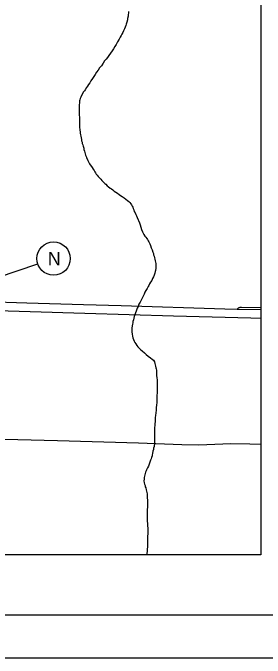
# Model space of a CAD drawing. Extents: x 1651.5 to 1685.5, y 1084.6 to 1106.6.
# Drawn here: x 1665.81 to 1668.74, y 1084.6 to 1092.09 of the extents above; entities that cross this region are included whole.
import ezdxf

# ---------------------------------------------------------------- set-up
doc = ezdxf.new("R2010")
doc.units = 0
for name, color, linetype in [('GM_X_County_Road', 7, 'Continuous'), ('GM_X_Interchange_Ramps', 7, 'Continuous'), ('GM_X_Minor_River', 7, 'Continuous'), ('GM_X_State_Route', 7, 'Continuous'), ('SC_Scratch1', 7, 'Continuous'), ('SH_Border', 7, 'Continuous'), ('SH_Data', 7, 'Continuous'), ('SH_Text', 7, 'Continuous')]:
    doc.layers.add(name, color=color, linetype=linetype)

msp = doc.modelspace()

# ---------------------------------------------------------------- linework, layer by layer
at = {"layer": 'GM_X_County_Road'}
msp.add_lwpolyline([(1664.5355, 1087.1696), (1664.9949, 1087.1576), (1665.8697, 1087.1385), (1666.329, 1087.1234), (1667.2696, 1087.0978), (1667.7725, 1087.0776), (1667.9694, 1087.0752), (1668.3411, 1087.089), (1668.5599, 1087.0865), (1668.6882, 1087.0829)], dxfattribs=at)
at = {"layer": 'GM_X_Interchange_Ramps'}
msp.add_lwpolyline([(1668.6882, 1088.6662), (1668.4646, 1088.6689), (1668.4591, 1088.6687), (1668.4539, 1088.6681), (1668.4487, 1088.6676), (1668.4426, 1088.6666), (1668.4361, 1088.6647), (1668.4322, 1088.6634), (1668.4284, 1088.6617), (1668.424, 1088.6596), (1668.4194, 1088.6571), (1668.4149, 1088.6535), (1668.4116, 1088.6492)], dxfattribs=at)
at = {"layer": 'GM_X_Minor_River'}
for points in [[(1667.1537, 1092.1007), (1667.1537, 1092.0846), (1667.151, 1092.0685), (1667.1482, 1092.0472), (1667.1428, 1092.0231), (1667.1401, 1092.007), (1667.132, 1091.9803), (1667.1266, 1091.9563), (1667.1213, 1091.9402), (1667.1132, 1091.9215), (1667.1051, 1091.9001), (1667.097, 1091.8788), (1667.0863, 1091.8574), (1667.0755, 1091.8387), (1667.0675, 1091.8227), (1667.0567, 1091.804), (1667.046, 1091.7826), (1667.0272, 1091.7506), (1667.0084, 1091.7212), (1666.9949, 1091.6945), (1666.9788, 1091.6705), (1666.9627, 1091.6464), (1666.9439, 1091.6171), (1666.9251, 1091.5904), (1666.909, 1091.569)], [(1666.909, 1091.569), (1666.8929, 1091.5503), (1666.8768, 1091.529), (1666.8607, 1091.5049), (1666.8419, 1091.4729), (1666.8178, 1091.4489), (1666.8016, 1091.4222), (1666.7829, 1091.3982), (1666.7667, 1091.3715), (1666.7506, 1091.3501), (1666.7372, 1091.3261), (1666.7184, 1091.2994), (1666.705, 1091.2754), (1666.6889, 1091.2567), (1666.6781, 1091.238), (1666.6674, 1091.2193), (1666.6513, 1091.1953), (1666.6432, 1091.1819), (1666.6325, 1091.1686), (1666.6083, 1091.1285), (1666.6002, 1091.1071), (1666.5922, 1091.0911), (1666.5895, 1091.0777), (1666.5868, 1091.0644), (1666.584, 1091.0403), (1666.5813, 1091.0243), (1666.5813, 1091.0109), (1666.5812, 1090.9948), (1666.5812, 1090.9788), (1666.5812, 1090.9627), (1666.5811, 1090.9413), (1666.5811, 1090.9226), (1666.581, 1090.9012), (1666.5836, 1090.8771), (1666.5836, 1090.8584), (1666.5835, 1090.8343), (1666.5835, 1090.8075), (1666.5834, 1090.7835), (1666.5834, 1090.7647), (1666.586, 1090.7513), (1666.5887, 1090.7379), (1666.5887, 1090.7246), (1666.5913, 1090.7059), (1666.5939, 1090.6925), (1666.5965, 1090.6711), (1666.6019, 1090.655), (1666.6045, 1090.6362), (1666.6071, 1090.6175), (1666.6098, 1090.6015), (1666.6151, 1090.588), (1666.6177, 1090.572), (1666.623, 1090.5559), (1666.6257, 1090.5399), (1666.6337, 1090.5158), (1666.6363, 1090.5024), (1666.6416, 1090.4809), (1666.6469, 1090.4649), (1666.6522, 1090.4515), (1666.6549, 1090.4354), (1666.6629, 1090.422), (1666.6655, 1090.4059), (1666.6735, 1090.3925), (1666.6815, 1090.3738), (1666.6921, 1090.3524), (1666.7028, 1090.3336), (1666.7321, 1090.2907), (1666.7428, 1090.2746), (1666.7535, 1090.2585), (1666.7615, 1090.2424), (1666.7721, 1090.229), (1666.7801, 1090.2156), (1666.7881, 1090.2022), (1666.8015, 1090.1888), (1666.8175, 1090.1727), (1666.8308, 1090.1566), (1666.8442, 1090.1432), (1666.8575, 1090.1298), (1666.8789, 1090.1083), (1666.8922, 1090.0976), (1666.9056, 1090.0815), (1666.9189, 1090.0734), (1666.9403, 1090.0546), (1666.9563, 1090.0438), (1666.9697, 1090.0331), (1666.9884, 1090.0197), (1667.0044, 1090.0062), (1667.0258, 1089.9928), (1667.0445, 1089.9793), (1667.0605, 1089.9686), (1667.0792, 1089.9578), (1667.1033, 1089.9417), (1667.122, 1089.9256), (1667.1433, 1089.9095), (1667.1567, 1089.8987), (1667.17, 1089.8853), (1667.1807, 1089.8719), (1667.1887, 1089.8585), (1667.194, 1089.8451), (1667.202, 1089.8317), (1667.2073, 1089.8183), (1667.2153, 1089.7995)], [(1667.2153, 1089.7995), (1667.2206, 1089.7808), (1667.2313, 1089.7674), (1667.2393, 1089.7486), (1667.2473, 1089.7299), (1667.2553, 1089.7111), (1667.2792, 1089.6495), (1667.2872, 1089.6281), (1667.2951, 1089.6013), (1667.3031, 1089.5718), (1667.3137, 1089.5451), (1667.3297, 1089.5156), (1667.3431, 1089.4968), (1667.3537, 1089.4834), (1667.3644, 1089.47), (1667.3724, 1089.4566), (1667.3804, 1089.4432), (1667.3884, 1089.4298), (1667.3991, 1089.4083), (1667.407, 1089.3869), (1667.4177, 1089.3601), (1667.4283, 1089.336), (1667.4336, 1089.3119), (1667.4416, 1089.2931), (1667.4443, 1089.2798), (1667.4496, 1089.2637), (1667.4549, 1089.2449), (1667.4575, 1089.2289), (1667.4628, 1089.2101), (1667.4655, 1089.1941), (1667.4681, 1089.178), (1667.4681, 1089.162), (1667.468, 1089.1405), (1667.468, 1089.1245), (1667.4652, 1089.0978), (1667.4625, 1089.0844), (1667.4571, 1089.0657), (1667.4517, 1089.0443), (1667.4437, 1089.0256), (1667.4329, 1089.0042), (1667.4222, 1088.9829), (1667.4087, 1088.9615), (1667.398, 1088.9428), (1667.3899, 1088.9241), (1667.3792, 1088.9108), (1667.3711, 1088.8867), (1667.355, 1088.8653), (1667.3442, 1088.8467), (1667.3335, 1088.8226), (1667.32, 1088.7905), (1667.3039, 1088.7612), (1667.2878, 1088.7318), (1667.2744, 1088.7051), (1667.2636, 1088.681), (1667.2529, 1088.6597), (1667.2448, 1088.6383), (1667.2205, 1088.5635), (1667.2151, 1088.5447), (1667.2097, 1088.5233), (1667.2043, 1088.5073), (1667.2016, 1088.4913), (1667.1989, 1088.4752), (1667.1962, 1088.4538), (1667.1934, 1088.4298), (1667.1934, 1088.4084), (1667.1933, 1088.3843), (1667.196, 1088.3602), (1667.1986, 1088.3361), (1667.2039, 1088.3174), (1667.2092, 1088.2986), (1667.2172, 1088.2772), (1667.2278, 1088.2611), (1667.2385, 1088.245), (1667.2492, 1088.2289), (1667.2625, 1088.2128), (1667.2759, 1088.1967), (1667.2919, 1088.1806), (1667.3132, 1088.1645), (1667.3373, 1088.1403), (1667.356, 1088.1242), (1667.38, 1088.1054), (1667.4067, 1088.0839), (1667.4281, 1088.0678), (1667.4414, 1088.0571), (1667.4548, 1088.0383), (1667.4601, 1088.0169), (1667.4627, 1088.0035), (1667.4654, 1087.9874), (1667.4707, 1087.9687), (1667.4733, 1087.9553), (1667.476, 1087.9419), (1667.4759, 1087.9232), (1667.4759, 1087.9045), (1667.4785, 1087.8804), (1667.4811, 1087.8536), (1667.4837, 1087.8295), (1667.4863, 1087.7974), (1667.4863, 1087.776), (1667.4862, 1087.7493), (1667.4862, 1087.7252), (1667.4861, 1087.6957)], [(1667.4861, 1087.6957), (1667.4833, 1087.6289), (1667.4832, 1087.6101), (1667.4832, 1087.5887), (1667.4805, 1087.5647), (1667.4777, 1087.5352), (1667.475, 1087.5085), (1667.4722, 1087.4764), (1667.4695, 1087.4443), (1667.4667, 1087.4149), (1667.464, 1087.3908), (1667.4613, 1087.3667), (1667.4612, 1087.3427), (1667.4585, 1087.3213), (1667.4584, 1087.2972), (1667.4557, 1087.2785), (1667.4556, 1087.2544), (1667.4556, 1087.2196), (1667.4555, 1087.1902), (1667.4554, 1087.1634), (1667.4527, 1087.1394), (1667.4527, 1087.1179), (1667.4526, 1087.0965), (1667.4526, 1087.0805), (1667.4499, 1087.0671), (1667.4498, 1087.0537), (1667.4445, 1087.0377), (1667.4417, 1087.0217), (1667.4363, 1087.0003), (1667.4309, 1086.9762), (1667.4282, 1086.9602), (1667.4255, 1086.9468), (1667.4201, 1086.9281), (1667.4147, 1086.9121), (1667.4093, 1086.8987), (1667.404, 1086.8853), (1667.3959, 1086.864), (1667.3878, 1086.8399), (1667.3851, 1086.8265), (1667.3743, 1086.8079), (1667.3636, 1086.7865), (1667.3582, 1086.7731), (1667.3501, 1086.7571), (1667.3339, 1086.6956), (1667.3339, 1086.6769), (1667.3312, 1086.6582), (1667.3365, 1086.6341), (1667.3391, 1086.618), (1667.3444, 1086.6046), (1667.3471, 1086.5886), (1667.3524, 1086.5751), (1667.3577, 1086.5537), (1667.3603, 1086.5377), (1667.3657, 1086.5216), (1667.3683, 1086.5082), (1667.3709, 1086.4841), (1667.3709, 1086.4708), (1667.3709, 1086.4574), (1667.3735, 1086.4386), (1667.3734, 1086.4146), (1667.3733, 1086.3611), (1667.3705, 1086.3183), (1667.3705, 1086.2835), (1667.3704, 1086.2487), (1667.3703, 1086.2166), (1667.3702, 1086.1898), (1667.3729, 1086.1631), (1667.3728, 1086.1336), (1667.3754, 1086.1069), (1667.3753, 1086.0721), (1667.3753, 1086.0453), (1667.3752, 1086.0106), (1667.3751, 1085.9785), (1667.375, 1085.9437), (1667.3723, 1085.9142), (1667.3722, 1085.8902), (1667.3695, 1085.8661), (1667.3694, 1085.8393), (1667.3667, 1085.8126), (1667.3656, 1085.8005)]]:
    msp.add_lwpolyline(points, dxfattribs=at)
at = {"layer": 'GM_X_State_Route'}
for points in [[(1653.9882, 1089.0716), (1654.5206, 1089.0563), (1655.2182, 1089.0358), (1655.7006, 1089.0196), (1656.1829, 1089.0075), (1657.0775, 1088.9829), (1657.4657, 1088.9713), (1658.3454, 1088.9451), (1660.4221, 1088.8844), (1661.0999, 1088.8659), (1661.6244, 1088.8494), (1662.2585, 1088.8312), (1663.3078, 1088.8007), (1664.1166, 1088.777), (1664.5833, 1088.7638), (1664.6413, 1088.7624), (1665.4938, 1088.737), (1665.9748, 1088.7239), (1666.6305, 1088.7038), (1667.0677, 1088.6901), (1668.268, 1088.6514), (1668.4116, 1088.6492), (1668.6882, 1088.6439)], [(1653.9882, 1088.972), (1654.9177, 1088.9448), (1655.9668, 1088.9137), (1656.6661, 1088.8935), (1657.4608, 1088.8688), (1658.0564, 1088.8506), (1658.4943, 1088.8393), (1659.3219, 1088.8187), (1660.1311, 1088.7948), (1661.7276, 1088.748), (1662.3619, 1088.7295), (1662.8212, 1088.7178), (1663.9585, 1088.6833), (1664.5805, 1088.6652), (1665.2488, 1088.6454), (1666.6484, 1088.6041), (1667.6764, 1088.5732), (1668.5696, 1088.5488), (1668.6882, 1088.5445)]]:
    msp.add_lwpolyline(points, dxfattribs=at)
at = {"layer": 'SC_Scratch1'}
msp.add_lwpolyline([(1651.4632, 1106.6005), (1685.4632, 1106.6005), (1685.4632, 1084.6005), (1651.4632, 1084.6005)], close=True, dxfattribs=at)
at = {"layer": 'SH_Border'}
msp.add_lwpolyline([(1651.9632, 1106.1005), (1684.9632, 1106.1005), (1684.9632, 1085.1005), (1651.9632, 1085.1005)], close=True, dxfattribs=at)
at = {"layer": 'SH_Data'}
msp.add_lwpolyline([(1653.9882, 1105.4005), (1668.6882, 1105.4005), (1668.6882, 1085.8005), (1653.9882, 1085.8005)], close=True, dxfattribs=at)
at = {"layer": 'SH_Text'}
msp.add_line((1665.5576, 1088.9926), (1666.1003, 1089.1761), dxfattribs=at)
msp.add_circle((1666.2844, 1089.236), 0.1936, dxfattribs=at)

# ---------------------------------------------------------------- texts
msp.add_text('N', height=0.156, dxfattribs=at).set_placement((1666.2175, 1089.158))

doc.saveas('drawing.dxf')
